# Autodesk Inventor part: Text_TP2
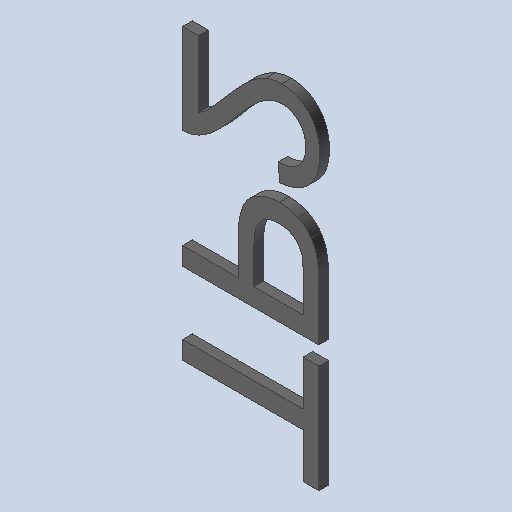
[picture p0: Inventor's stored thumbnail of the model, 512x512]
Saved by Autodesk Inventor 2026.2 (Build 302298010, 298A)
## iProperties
Created: 2026-10
Part Number: Text_TP2
Material: Générique
Document SubType Name: Modeling
Designer: mel
Density: 1 g/cm^3
Appearance: Par défaut
Author: mel
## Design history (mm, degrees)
feature "Base1"
feature "Base2"
feature "Base3"
node "Solide1"
node "Solide2"
node "Solide3"
